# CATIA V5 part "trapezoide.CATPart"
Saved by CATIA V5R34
Part number: trapezoide
Bounding box of the stored display mesh (mm): x -4.5 to 4.5, y -4.793 to 4.793, z -6 to 0
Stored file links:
  C:\Users\Apolinar\Desktop\cnc\trapezoide.CATPart
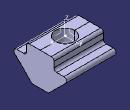
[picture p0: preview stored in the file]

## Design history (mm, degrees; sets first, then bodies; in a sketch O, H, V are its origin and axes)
AxisSystem1: origin (0, 0, 0), X (1, 0, 0), Y (0, 1, 0), Z (0, 0, 1)
Body1 (main body)
  Sketch1 on YZ plane of AxisSystem1, origin (0, 0, 0), H (0, 1, 0), V (0, 0, 1)
    line L1 (0, 0) -> (2.5, 0)
    point P1 (2.5, 0)
    line L2 (2.5, 0) -> (2.5, -2)
    point P2 (2.5, -2)
    line L3 (2.5, -2) -> (5.5, -2)
    point P3 (5.5, -2)
    line L4 (5.5, -2) -> (1.5, -6)
    point P4 (1.5, -6)
    line L5 (1.5, -6) -> (0, -6)
    point P5 (0, -6)
    point P6 (-2.5, -2)
    point P7 (-5.5, -2)
    point P8 (-1.5, -6)
    point P9 (0, -6)
    line L6 (-2.5, -2) -> (-5.5, -2)
    line L7 (-5.5, -2) -> (-1.5, -6)
    line L8 (-1.5, -6) -> (0, -6)
    point P10 (-2.5, 0)
    point P11 (0, 0)
    line L9 (0, 0) -> (-2.5, 0)
    line L10 (-2.5, 0) -> (-2.5, -2)
    distance L3 L1 = 2
    distance L2 V = 2.5
    distance P3 V = 5.5
    distance L3 L5 = 4
    length L5 = 1.5
    horizontal: L1 H, L3 H, L5 H
    vertical: L2 V
    coincidence: P5 V, O P11, P5 P9
    symmetry: P2 P6 V, P3 P7 V, P4 P8 V, P5 P9 V, L3 L6 V, L4 L7 V, L5 L8 V, P1 P10 V, O P11 V, L1 L9 V, L2 L10 V
  Pad1: profile Sketch1, direction (1, 0, 0), length 4.5, mirrored extent
  Sketch2 on face of Pad1 from Sketch1.L5, origin (0, 0, -6), H (1, 0, 0), V (0, -1, 0)
    point P1 (2.7, 0)
    construction circle A1 centre (0, 0) radius 3.1177
    construction circle A2 centre (0, 0) radius 2.7
    point P2 (2.7, -1.5588)
    point P3 (2.7, 1.5588)
    point P4 (0, 3.1177)
    point P5 (-2.7, 1.5588)
    point P6 (-2.7, -1.5588)
    point P7 (0, -3.1177)
    line L1 (2.7, -1.5588) -> (2.7, 1.5588)
    line L2 (2.7, 1.5588) -> (0, 3.1177)
    line L3 (0, 3.1177) -> (-2.7, 1.5588)
    line L4 (-2.7, 1.5588) -> (-2.7, -1.5588)
    line L5 (-2.7, -1.5588) -> (0, -3.1177)
    line L6 (0, -3.1177) -> (2.7, -1.5588)
    construction line L7 (0, 0) -> (2.7, 0)
    distance L2 L5 = 5.4
    coincidence: A1 P2, A1 P3, A1 P4, A1 P5, A1 P6, A1 P7
    tangency: A2 L1, A2 L2, A2 L3, A2 L4, A2 L5, A2 L6
    midpoint: P1 L1
    horizontal: L7 H
  Pocket1: profile Sketch2, direction (0, 0, 1), length 3
  Sketch3 on end face of Pocket1, origin (0, 0, -3), H (1, 0, 0), V (0, -1, 0)
    circle A1 centre (0, 0) radius 1.75
    radius A1 = 1.75
  Pocket2: profile Sketch3, direction (0, 0, 1), through (limit type 6)
  Fillet1: radius 0.5, on edge [face of Pad1 from Sketch1.L3 | face of Pad1 from Sketch1.L4]; edge [face of Pad1 from Sketch1.L2 | face of Pad1 from Sketch1.L3]; edge [face of Pad1 from Sketch1.L1 | face of Pad1 from Sketch1.L2]; edge [face of Pad1 from Sketch1.L7 | face of Pad1 from Sketch1.L6]; edge [face of Pad1 from Sketch1.L6 | face of Pad1 from Sketch1.L10]; edge [face of Pad1 from Sketch1.L10 | face of Pad1 from Sketch1.L9]; edge [face of Pad1 from Sketch1.L4 | face of Pad1 from Sketch1.L5] (x2); edge [face of Pad1 from Sketch1.L8 | face of Pad1 from Sketch1.L7] (x2)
